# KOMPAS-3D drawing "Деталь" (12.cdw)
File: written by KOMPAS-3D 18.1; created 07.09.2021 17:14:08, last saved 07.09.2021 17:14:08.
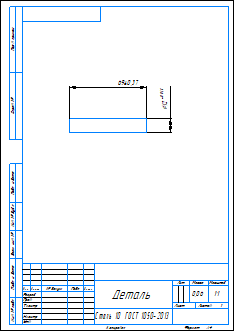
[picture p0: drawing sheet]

Sheet 1: A4, portrait

Document properties: Автор: 111; Полное имя файла: C:\Users\admin\Desktop\ffb\12.cdw; Масса: 0.061306

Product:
- Part/product: Деталь
    Масса: 0.061306

Title block, sheet 1: Наименование: Деталь; Материал: Сталь 10  ГОСТ 1050-2013; Масса: 0,06; Количество листов документа: 1; Форматы листов документа: A4

Views: Вид 1, Спереди
Referenced files in C:\Users\admin\Desktop\ffb\: 12.m3d
Dimensions and other numbers on the sheet: 69±0,37; 12; 1:1; 1; 0,06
